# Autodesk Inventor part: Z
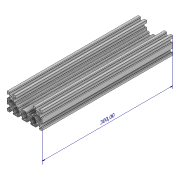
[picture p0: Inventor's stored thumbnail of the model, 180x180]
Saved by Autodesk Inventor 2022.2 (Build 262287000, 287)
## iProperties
Created: 2024-09
Part Number: Z
Material: solidworks materials|6063-T5
Document SubType Name: Modeling
Designer: 18907419
Density: 2.7 g/cm^3
Appearance: Default
Author: 18907419
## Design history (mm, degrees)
node "Annotazioni"
  node "Quota lineare 1" dims "d1" = 300 (derived)
feature "Solido1"
node "Solido2"
other parameters: "d0" = 5.1386 (derived)
